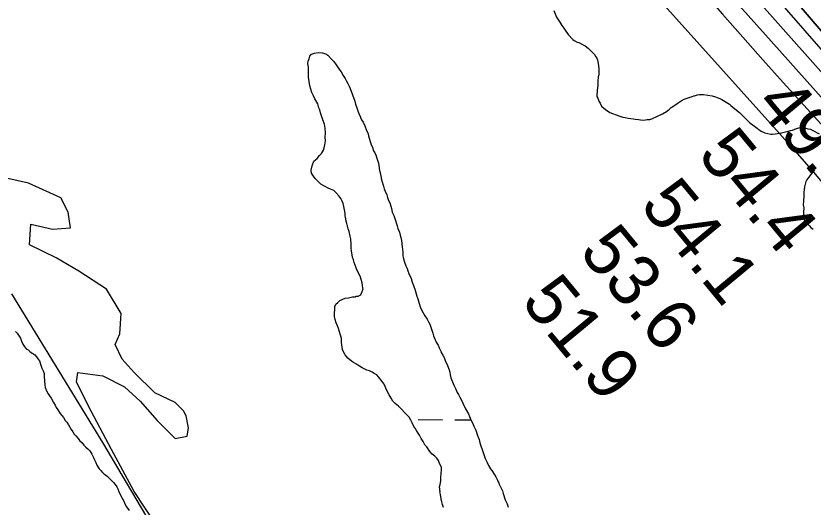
# Model space of a CAD drawing. Extents: x 3172231 to 3210228, y 940198 to 965780.
# Drawn here: x 3189862 to 3190904, y 947185 to 947827 of the extents above; entities that cross this region are included whole.
import ezdxf

# ---------------------------------------------------------------- set-up
doc = ezdxf.new("R2010")
doc.units = 0
for name, color, linetype in [('V-BORW-LINE', 7, 'Continuous'), ('V-RIVR-RANG', 7, 'Continuous'), ('V-SITE-VEGE', 7, 'Continuous'), ('V-TOPO-DPTH', 7, 'Continuous'), ('V-TOPO-MAJR', 7, 'Continuous'), ('V-TOPO-MINR', 7, 'Continuous'), ('V-TOPO-SHOR', 7, 'Continuous'), ('V-WETL-SWMP', 7, 'Continuous')]:
    doc.layers.add(name, color=color, linetype=linetype)

msp = doc.modelspace()

# ---------------------------------------------------------------- linework, layer by layer
at = {"layer": 'V-BORW-LINE'}
for points in [[(3189975.602, 947269.793), (3189856.583, 947463.779)], [(3190101.875, 947056.304), (3189975.602, 947269.793)]]:
    msp.add_lwpolyline(points, dxfattribs=at)
at = {"layer": 'V-SITE-VEGE'}
for p, q in [((3190565.084, 947834.244), (3190568.543, 947825.358)), ((3190568.543, 947825.358), (3190572.799, 947819.022)), ((3190572.799, 947819.022), (3190575.261, 947814.561)), ((3190575.261, 947814.561), (3190578.107, 947810.826)), ((3190578.107, 947810.826), (3190579.514, 947808.223)), ((3190579.514, 947808.223), (3190583.786, 947802.619)), ((3190583.786, 947802.619), (3190589.873, 947796.24)), ((3190589.873, 947796.24), (3190591.671, 947794.73)), ((3190591.671, 947794.73), (3190595.296, 947792.809)), ((3190595.296, 947792.809), (3190597.488, 947792.392)), ((3190597.488, 947792.392), (3190603.285, 947789.32)), ((3190603.285, 947789.32), (3190605.819, 947787.794)), ((3190605.819, 947787.794), (3190609.782, 947784.765)), ((3190609.782, 947784.765), (3190611.93, 947782.512)), ((3190611.93, 947782.512), (3190618.025, 947776.499)), ((3190618.025, 947776.499), (3190619.79, 947773.523)), ((3190619.79, 947773.523), (3190621.216, 947771.656)), ((3190621.216, 947771.656), (3190621.896, 947769.438)), ((3190621.896, 947769.438), (3190622.211, 947767.23)), ((3190622.211, 947767.23), (3190622.885, 947764.645)), ((3190622.885, 947764.645), (3190623.837, 947758.387)), ((3190623.837, 947758.387), (3190623.641, 947749.953)), ((3190622.846, 947747.401), (3190622.334, 947741.177)), ((3190623.641, 947749.953), (3190622.846, 947747.401)), ((3190622.211, 947736.045), (3190621.332, 947729.825)), ((3190622.334, 947741.177), (3190622.211, 947736.045)), ((3190621.332, 947729.825), (3190621.144, 947721.76)), ((3190621.144, 947721.76), (3190622.191, 947719.534)), ((3190735.164, 947718.344), (3190745.517, 947721.772)), ((3190745.517, 947721.772), (3190747.735, 947722.454)), ((3190747.735, 947722.454), (3190748.837, 947722.428)), ((3190748.837, 947722.428), (3190752.538, 947723.808)), ((3190752.538, 947723.808), (3190755.12, 947724.482)), ((3190755.12, 947724.482), (3190760.621, 947724.353)), ((3190760.621, 947724.353), (3190771.955, 947722.618)), ((3190771.955, 947722.618), (3190775.963, 947721.424)), ((3190775.963, 947721.424), (3190778.146, 947720.64)), ((3190622.191, 947719.534), (3190623.571, 947715.833)), ((3190623.571, 947715.833), (3190625.336, 947712.855)), ((3190625.336, 947712.855), (3190627.083, 947709.146)), ((3190721.75, 947709.491), (3190727.343, 947713.394)), ((3190727.343, 947713.394), (3190731.081, 947716.241)), ((3190731.081, 947716.241), (3190735.164, 947718.344)), ((3190778.146, 947720.64), (3190781.777, 947719.085)), ((3190781.777, 947719.085), (3190784.318, 947717.924)), ((3190784.318, 947717.924), (3190792.273, 947712.968)), ((3190792.273, 947712.968), (3190794.448, 947711.817)), ((3190794.448, 947711.817), (3190796.238, 947709.941)), ((3190627.083, 947709.146), (3190632.48, 947704.616)), ((3190632.48, 947704.616), (3190637.895, 947700.821)), ((3190637.895, 947700.821), (3190649.9, 947696.502)), ((3190706.83, 947699.199), (3190712.034, 947702.013)), ((3190712.034, 947702.013), (3190713.902, 947703.437)), ((3190713.902, 947703.437), (3190716.145, 947705.218)), ((3190716.145, 947705.218), (3190718.397, 947707.367)), ((3190718.397, 947707.367), (3190721.75, 947709.491)), ((3190796.238, 947709.941), (3190801.268, 947705.419)), ((3190801.268, 947705.419), (3190807.397, 947700.873)), ((3190807.397, 947700.873), (3190811.346, 947697.11)), ((3190649.9, 947696.502), (3190655, 947694.915)), ((3190655, 947694.915), (3190657.916, 947694.112)), ((3190657.916, 947694.112), (3190661.932, 947693.285)), ((3190661.932, 947693.285), (3190668.883, 947692.388)), ((3190668.883, 947692.388), (3190671.072, 947691.97)), ((3190671.072, 947691.97), (3190675.473, 947691.863)), ((3190675.473, 947691.863), (3190678.023, 947691.073)), ((3190678.023, 947691.073), (3190682.422, 947690.968)), ((3190682.422, 947690.968), (3190686.842, 947691.599)), ((3190686.842, 947691.599), (3190690.516, 947691.88)), ((3190690.516, 947691.88), (3190693.1, 947692.552)), ((3190693.1, 947692.552), (3190700.52, 947696.047)), ((3190700.52, 947696.047), (3190706.83, 947699.199)), ((3190811.346, 947697.11), (3190817.433, 947690.733)), ((3190817.433, 947690.733), (3190820.664, 947687.718)), ((3190820.664, 947687.718), (3190830.4, 947680.52)), ((3190830.4, 947680.52), (3190832.557, 947678.635)), ((3190876.935, 947677.96), (3190882.121, 947680.038)), ((3190882.121, 947680.038), (3190886.921, 947681.392)), ((3190886.921, 947681.392), (3190889.131, 947681.707)), ((3190889.131, 947681.707), (3190891.691, 947681.281)), ((3190891.691, 947681.281), (3190896.79, 947679.694)), ((3190896.79, 947679.694), (3190900.071, 947678.883)), ((3190832.557, 947678.635), (3190835.807, 947676.356)), ((3190835.807, 947676.356), (3190840.53, 947674.412)), ((3190840.53, 947674.412), (3190848.554, 947672.389)), ((3190848.554, 947672.389), (3190850.764, 947672.704)), ((3190850.764, 947672.704), (3190854.44, 947672.985)), ((3190854.44, 947672.985), (3190862.173, 947674.269)), ((3190862.173, 947674.269), (3190865.864, 947675.283)), ((3190865.864, 947675.283), (3190871.027, 947676.264)), ((3190871.027, 947676.264), (3190873.986, 947677.296)), ((3190873.986, 947677.296), (3190876.935, 947677.96)), ((3190900.071, 947678.883), (3190903.338, 947677.339)), ((3190903.338, 947677.339), (3190911.675, 947673.106)), ((3190902.027, 947621.603), (3190897.855, 947615.829)), ((3190905.431, 947625.926), (3190902.027, 947621.603)), ((3189878.318, 947608.334), (3189851.594, 947614.625)), ((3189920.765, 947589.457), (3189878.318, 947608.334)), ((3190893.249, 947607.134), (3190892.438, 947603.851)), ((3190894.069, 947610.781), (3190893.249, 947607.134)), ((3190895.211, 947612.589), (3190894.069, 947610.781)), ((3190897.855, 947615.829), (3190895.211, 947612.589)), ((3190891.531, 947596.533), (3190891.429, 947592.134)), ((3190892.438, 947603.851), (3190891.531, 947596.533)), ((3189930.198, 947570.581), (3189920.765, 947589.457)), ((3190891.429, 947592.134), (3190890.907, 947585.541)), ((3190890.907, 947585.541), (3190890.778, 947580.041)), ((3190890.778, 947580.041), (3190891.425, 947576.356)), ((3190891.425, 947576.356), (3190890.921, 947570.499)), ((3189933.342, 947550.132), (3189930.198, 947570.581)), ((3190890.921, 947570.499), (3190891.482, 947563.149)), ((3189879.891, 947528.109), (3189881.464, 947554.85)), ((3189881.464, 947554.85), (3189909.761, 947548.559)), ((3190891.482, 947563.149), (3190892.154, 947560.566)), ((3190892.154, 947560.566), (3190893.209, 947558.704)), ((3190893.209, 947558.704), (3190898.941, 947552.7)), ((3189909.761, 947548.559), (3189933.342, 947550.132)), ((3190898.941, 947552.7), (3190900.723, 947550.457)), ((3190900.723, 947550.457), (3190903.612, 947548.555)), ((3189914.478, 947510.806), (3189879.891, 947528.109)), ((3189944.348, 947493.502), (3189914.478, 947510.806)), ((3189980.505, 947469.905), (3189944.348, 947493.502)), ((3189999.367, 947438.446), (3189980.505, 947469.905)), ((3189997.798, 947411.703), (3189999.367, 947438.446)), ((3189991.511, 947397.547), (3189997.798, 947411.703)), ((3190000.942, 947378.671), (3189991.511, 947397.547)), ((3190016.662, 947361.367), (3190000.942, 947378.671)), ((3189941.204, 947348.782), (3189942.775, 947361.367)), ((3189942.775, 947361.367), (3189975.788, 947356.649)), ((3190043.389, 947334.625), (3190016.662, 947361.367)), ((3189956.922, 947317.321), (3189941.204, 947348.782)), ((3189975.788, 947356.649), (3190004.086, 947342.491)), ((3190004.086, 947342.491), (3190024.525, 947323.615)), ((3190070.115, 947322.042), (3190043.389, 947334.625)), ((3189986.792, 947260.694), (3189956.922, 947317.321)), ((3190024.525, 947323.615), (3190046.533, 947298.447)), ((3190081.119, 947311.03), (3190070.115, 947322.042)), ((3190084.265, 947304.738), (3190081.119, 947311.03)), ((3190087.409, 947289.007), (3190084.265, 947304.738)), ((3190046.533, 947298.447), (3190070.115, 947274.85)), ((3190085.836, 947277.995), (3190087.409, 947289.007)), ((3190070.115, 947274.85), (3190085.836, 947277.995)), ((3190016.662, 947205.635), (3189986.792, 947260.694)), ((3190043.389, 947164.739), (3190016.662, 947205.635))]:
    msp.add_line(p, q, dxfattribs=at)
at = {"layer": 'V-TOPO-DPTH'}
msp.add_lwpolyline([(3191003.798, 947703.104), (3190371.389, 948440.144)], dxfattribs=at)
at = {"layer": 'V-TOPO-MAJR'}
msp.add_lwpolyline([(3190780.826, 947870.291), (3190841.33, 947802.226), (3190925.193, 947708.779), (3190944.226, 947687.848), (3190963.438, 947667.086), (3190982.921, 947646.576), (3191002.583, 947626.236), (3191916.297, 946926.02), (3191939.622, 946908.908), (3191943.668, 946905.677), (3191947.52, 946902.246), (3191951.081, 946898.512), (3191954.447, 946894.578), (3191965.03, 946881.133)], dxfattribs=at)
at = {"layer": 'V-TOPO-MINR'}
for points in [[(3189654.756, 949405.366), (3190276.246, 948537.001), (3190281.623, 948529.611), (3190287.075, 948522.279), (3190292.642, 948515.033), (3190298.284, 948507.844), (3190380.452, 948404.824), (3190427.618, 948346.486), (3190475.293, 948288.575), (3190523.733, 948231.301), (3190572.682, 948174.452), (3190982.548, 947704.784), (3190988.103, 947698.499), (3190993.711, 947692.263), (3190999.397, 947686.099), (3191005.137, 947679.982), (3191821.886, 947045.773), (3191936.602, 946961.604), (3191956.768, 946945.504), (3191975.964, 946928.401), (3191993.708, 946909.795), (3192010.483, 946890.186), (3192012.814, 946887.224)], [(3189271.701, 949283.317), (3190177.18, 948464.824), (3190189.741, 948449.425), (3190202.355, 948434.07), (3190215.004, 948418.744), (3190349.973, 948255.782), (3190430.715, 948159.499), (3190512.233, 948063.886), (3190594.915, 947969.277), (3190678.373, 947875.339), (3190859.895, 947673.523), (3190883.501, 947646.818), (3190906.794, 947619.848), (3190929.619, 947592.48), (3190952.131, 947564.847), (3191055.723, 947435.429)], [(3189726.179, 949118.6), (3190220.44, 948473.312), (3190220.888, 948472.734), (3190221.342, 948472.162), (3190224.465, 948468.273), (3190226.272, 948466.057), (3190228.1, 948463.86), (3190229.961, 948461.69), (3190231.843, 948459.538), (3190243.425, 948446.5), (3190251.107, 948437.837), (3190258.778, 948429.164), (3190266.435, 948420.478), (3190274.081, 948411.783), (3190785.394, 947829.287), (3190811.718, 947799.441), (3190838.135, 947769.678), (3190864.693, 947740.041), (3190891.344, 947710.487), (3190918.132, 947681.057), (3190945.008, 947651.708), (3190972.017, 947622.481), (3190999.115, 947593.336), (3191258.344, 947315.778)], [(3190371.389, 948440.144), (3191003.798, 947703.104)], [(3190769.795, 947916.905), (3190955.962, 947706.712), (3190967.744, 947693.583), (3190979.637, 947680.557), (3190991.699, 947667.687), (3191003.873, 947654.92), (3191863.674, 946989.558), (3191868.763, 946986.139), (3191938.112, 946935.255), (3191950.218, 946925.59), (3191961.742, 946915.323), (3191972.393, 946904.153), (3191982.463, 946892.382), (3191992.769, 946879.29)]]:
    msp.add_lwpolyline(points, dxfattribs=at)
at = {"layer": 'V-TOPO-SHOR'}
for points in [[(3189861.539, 947414.896), (3189863.509, 947412.416), (3189865.276, 947409.94), (3189867.818, 947405.823), (3189869.354, 947402.135), (3189871.087, 947398.24), (3189872.85, 947395.561), (3189875.207, 947392.259), (3189875.203, 947392.057), (3189878.009, 947390.57), (3189880.591, 947388.278), (3189883.987, 947385.966), (3189886.782, 947384.076), (3189888.955, 947381.589), (3189890.723, 947379.113), (3189892.685, 947376.228), (3189894.385, 947370.911), (3189895.71, 947366.823), (3189897.452, 947363.333), (3189898.792, 947359.854), (3189899.111, 947356.194), (3189899.57, 947349.895), (3189899.66, 947345.022), (3189900.393, 947341.76), (3189902.298, 947336.439), (3189904.051, 947333.355), (3189906.017, 947330.672), (3189907.973, 947327.584), (3189911.287, 947321.825), (3189913.238, 947318.531), (3189914.795, 947315.656), (3189916.954, 947312.562), (3189919.102, 947309.061), (3189921.058, 947305.973), (3189921.85, 947305.144), (3189924.013, 947302.252), (3189926.565, 947298.541), (3189928.539, 947296.261), (3189930.694, 947292.964), (3189932.645, 947289.673), (3189934.403, 947286.792), (3189936.354, 947283.5), (3189938.32, 947280.815), (3189940.291, 947278.335), (3189943.455, 947274.813), (3189945.222, 947272.337), (3189948.394, 947269.22), (3189950.762, 947266.324), (3189953.34, 947263.827), (3189956.126, 947261.529), (3189958.501, 947259.039), (3189961.434, 947254.304), (3189963.564, 947249.993), (3189964.918, 947247.122), (3189966.255, 947243.642), (3189967.791, 947239.954), (3189970.931, 947235.417)], [(3189970.931, 947235.417), (3189972.903, 947232.935), (3189975.283, 947230.65), (3189977.068, 947228.985), (3189977.662, 947228.36), (3189981.257, 947225.841), (3189984.429, 947222.724), (3189987.003, 947220.027), (3189989.379, 947217.536), (3189991.552, 947215.05), (3189993.711, 947211.958), (3189995.062, 947209.084), (3189996.608, 947205.801), (3189999.117, 947200.266), (3190000.668, 947197.185), (3190003, 947192.87), (3190004.934, 947188.768), (3190006.687, 947185.684), (3190009.816, 947180.742)]]:
    msp.add_lwpolyline(points, dxfattribs=at)
at = {"layer": 'V-WETL-SWMP'}
for p, q in [((3190387.565, 947299.683), (3190419.564, 947299.465)), ((3190435.564, 947299.356), (3190456.448, 947299.214))]:
    msp.add_line(p, q, dxfattribs=at)
for points in [[(3190292.393, 947384.361), (3190290.191, 947388.347), (3190288.95, 947391.326), (3190287.52, 947400.212), (3190287.315, 947405.462), (3190286.729, 947408.426), (3190284.605, 947415.689), (3190283.691, 947418.661), (3190282.13, 947421.976), (3190280.584, 947425.946), (3190279.381, 947430.564), (3190278.491, 947434.519), (3190278.263, 947438.787), (3190278.699, 947443.366), (3190278.791, 947447.298), (3190280.179, 947450.544), (3190282.526, 947452.783), (3190285.201, 947455.016), (3190292.159, 947458.13), (3190296.762, 947458.678), (3190302.035, 947459.865), (3190305.647, 947460.108), (3190306.318, 947460.748), (3190309.275, 947461.007), (3190312.59, 947462.568), (3190314.336, 947467.117), (3190315.731, 947470.69), (3190315.411, 947471.025), (3190314.856, 947475.3), (3190314.27, 947478.265), (3190313.067, 947482.883), (3190312.153, 947485.855), (3190309.655, 947491.159), (3190307.454, 947495.145), (3190306.54, 947498.117), (3190304.073, 947504.732), (3190303.175, 947508.359), (3190301.949, 947511.994), (3190301.363, 947514.958), (3190300.495, 947519.896), (3190299.933, 947523.844), (3190300.04, 947528.431), (3190299.562, 947535.982), (3190298.984, 947539.274), (3190297.484, 947545.211), (3190296.258, 947548.846), (3190295.36, 947552.473), (3190294.454, 947555.773), (3190293.548, 947559.073), (3190292.962, 947562.037), (3190292.399, 947565.984), (3190292.148, 947569.268), (3190291.265, 947573.551), (3190290.39, 947578.161), (3190289.492, 947581.789), (3190288.258, 947585.096), (3190286.369, 947588.419), (3190283.833, 947592.085), (3190280.321, 947596.101), (3190277.441, 947599.12), (3190272.885, 947600.538), (3190269.967, 947601.918), (3190265.441, 947604.647), (3190260.588, 947607.384), (3190257.381, 947610.41), (3190252.886, 947614.45), (3190250.661, 947617.452), (3190248.46, 947621.438), (3190247.905, 947625.713), (3190249.019, 947631.26), (3190251.131, 947637.44), (3190255.468, 947640.616), (3190258.509, 947644.479), (3190261.2, 947647.366), (3190263.921, 947651.564), (3190264.653, 947654.825), (3190265.729, 947658.734), (3190266.507, 947663.961), (3190266.28, 947668.228), (3190266.418, 947674.126), (3190266.237, 947680.36), (3190265.05, 947685.633), (3190263.214, 947691.249), (3190259.826, 947700.508), (3190258.928, 947704.136), (3190258.014, 947707.108), (3190256.491, 947712.061), (3190252.713, 947718.707), (3190250.84, 947722.685), (3190248.646, 947726.998), (3190246.225, 947735.579), (3190245.373, 947741.172), (3190244.193, 947746.773), (3190244.424, 947756.603), (3190244.174, 947759.887), (3190243.626, 947764.49), (3190243.711, 947768.094), (3190245.091, 947771.012), (3190246.158, 947774.594), (3190248.178, 947776.841), (3190252.149, 947778.387)], [(3190252.149, 947778.387), (3190256.759, 947779.262), (3190261.994, 947778.811), (3190266.878, 947777.385), (3190269.788, 947775.678), (3190274.588, 947770.647), (3190277.46, 947767.301), (3190280.316, 947763.3), (3190283.797, 947757.973), (3190286.981, 947753.964), (3190289.823, 947749.307), (3190292.024, 947745.322), (3190293.6, 947742.662), (3190295.802, 947738.676), (3190297.363, 947735.361), (3190298.597, 947732.053), (3190302.008, 947723.777), (3190304.765, 947715.516), (3190305.663, 947711.889), (3190307.513, 947706.928), (3190308.732, 947702.965), (3190310.59, 947698.332), (3190312.151, 947695.017), (3190312.463, 947694.354), (3190313.697, 947691.046), (3190315.921, 947688.044), (3190318.107, 947683.402), (3190320.262, 947677.451), (3190321.823, 947674.136), (3190322.714, 947670.181), (3190326.376, 947658.62), (3190327.945, 947655.633), (3190329.468, 947650.679), (3190331.045, 947648.02), (3190332.919, 947644.041), (3190332.911, 947643.714), (3190333.832, 947641.069), (3190335.058, 947637.434), (3190335.644, 947634.47), (3190336.23, 947631.506), (3190337.059, 947624.929), (3190337.356, 947623.611), (3190338.254, 947619.984), (3190339.137, 947615.701), (3190339.442, 947614.71), (3190340.355, 947611.738), (3190342.48, 947604.476), (3190343.386, 947601.176), (3190344.299, 947598.204), (3190346.477, 947593.235), (3190347.703, 947589.6), (3190348.929, 947585.965), (3190350.491, 947582.65), (3190351.701, 947578.36), (3190352.615, 947575.388), (3190353.818, 947570.77), (3190355.683, 947566.464), (3190356.597, 947563.492), (3190357.823, 947559.857), (3190359.361, 947555.559), (3190360.275, 947552.587), (3190361.181, 947549.287), (3190363.039, 947544.654), (3190364.257, 947540.691), (3190365.163, 947537.391), (3190365.734, 947533.772), (3190366.844, 947525.222), (3190367.666, 947518.318), (3190367.55, 947513.403), (3190367.839, 947511.757), (3190368.441, 947509.448), (3190369.979, 947505.15), (3190371.509, 947500.524), (3190373.071, 947497.209), (3190374.304, 947493.902), (3190375.538, 947490.594), (3190378.333, 947483.972), (3190379.856, 947479.018), (3190381.729, 947475.04), (3190383.549, 947468.768), (3190385.072, 947463.815), (3190385.985, 947460.843), (3190387.211, 947457.208), (3190388.125, 947454.236), (3190389.039, 947451.264), (3190390.249, 947446.974), (3190392.435, 947442.332), (3190396.205, 947435.359), (3190399.382, 947431.023), (3190400.935, 947427.38), (3190402.832, 947424.385), (3190404.378, 947420.414), (3190406.814, 947412.489), (3190407.713, 947408.862), (3190408.954, 947405.882), (3190411.132, 947400.913), (3190413.661, 947396.92), (3190415.214, 947393.277), (3190417.713, 947387.973), (3190417.697, 947387.317), (3190419.906, 947383.659)], [(3190420.81, 947184.967), (3190419.592, 947188.93), (3190418.686, 947192.229), (3190417.468, 947196.192), (3190416.615, 947201.785), (3190416.037, 947205.077), (3190416.372, 947205.397), (3190415.544, 947211.973), (3190416.268, 947214.907), (3190417.359, 947219.471), (3190417.459, 947223.731), (3190417.598, 947229.629), (3190418.033, 947234.208), (3190418.11, 947237.485), (3190415.604, 947242.461), (3190414.051, 947246.104), (3190411.834, 947249.434), (3190409.267, 947251.79), (3190406.052, 947254.488), (3190402.852, 947257.841), (3190398.739, 947264.167), (3190396.507, 947266.842), (3190393.986, 947271.163), (3190391.457, 947275.157), (3190389.256, 947279.143), (3190387.679, 947281.803), (3190385.47, 947285.461), (3190383.901, 947288.448), (3190381.989, 947290.788), (3190379.803, 947295.429), (3190378.242, 947298.744), (3190375.713, 947302.738), (3190370.906, 947307.44), (3190364.834, 947314.14), (3190361.955, 947317.158), (3190357.772, 947320.535), (3190354.573, 947323.888), (3190352.364, 947327.547), (3190349.842, 947331.868), (3190346.697, 947337.515), (3190343.285, 947345.791), (3190340.421, 947349.465), (3190335.645, 947355.478), (3190333.413, 947358.153), (3190330.174, 947359.869), (3190327.592, 947361.568), (3190324.026, 947363.291), (3190320.445, 947364.359), (3190317.207, 947366.074), (3190314.289, 947367.454), (3190311.058, 947369.497), (3190308.795, 947370.862), (3190306.213, 947372.562), (3190302.974, 947374.277), (3190300.392, 947375.977), (3190295.569, 947380.024), (3190292.393, 947384.361)], [(3190419.906, 947383.659), (3190421.475, 947380.672), (3190423.029, 947377.029), (3190425.824, 947370.406), (3190427.979, 947364.455), (3190428.892, 947361.483), (3190429.471, 947358.191), (3190430.361, 947354.236), (3190434.07, 947344.641), (3190436.263, 947340.328), (3190438.761, 947335.024), (3190440.338, 947332.364), (3190442.227, 947329.041), (3190444.428, 947325.055), (3190445.974, 947321.085), (3190449.409, 947313.792), (3190453.187, 947307.146), (3190454.748, 947303.831), (3190456.286, 947299.533), (3190458.48, 947295.219), (3190460.353, 947291.241), (3190462.851, 947285.937), (3190464.679, 947279.993), (3190465.912, 947276.686), (3190467.154, 947273.706), (3190468.029, 947269.096), (3190469.583, 947265.453), (3190471.105, 947260.499), (3190472.651, 947256.529), (3190475.095, 947248.931), (3190477.593, 947243.627), (3190479.467, 947239.649), (3190481.988, 947235.328), (3190483.9, 947232.988), (3190486.741, 947228.331), (3190489.286, 947224.993), (3190491.152, 947220.688), (3190491.456, 947219.697), (3190492.401, 947218.035), (3190493.65, 947215.383), (3190496.148, 947210.079), (3190497.701, 947206.436), (3190498.607, 947203.137), (3190501.364, 947194.876), (3190503.862, 947189.572), (3190505.4, 947185.274)]]:
    msp.add_lwpolyline(points, dxfattribs=at)

# ---------------------------------------------------------------- texts
at = {"layer": 'V-RIVR-RANG'}
for s, p in [('49.0', (3190826.246, 947711.132)), ('54.4', (3190751.258, 947644.9)), ('54.1', (3190675.933, 947579.075)), ('53.6', (3190596.401, 947518.327)), ('51.9', (3190520.572, 947453.11))]:
    msp.add_text(s, height=67, rotation=309.648326, dxfattribs=at).set_placement(p)

doc.saveas('drawing.dxf')
